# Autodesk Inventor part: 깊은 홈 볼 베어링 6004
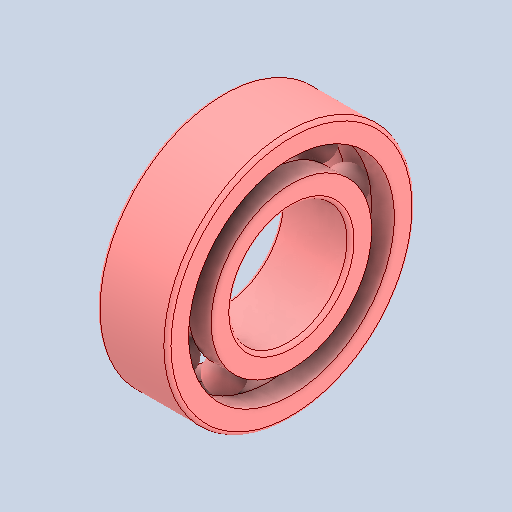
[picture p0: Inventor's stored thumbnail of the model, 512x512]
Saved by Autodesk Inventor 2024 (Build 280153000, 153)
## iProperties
Created: 2025-11
Part Number: 깊은 홈 볼 베어링 6004
Material: 강철, 연강
Description: 깊은 그루브 볼 베어링
Document SubType Name: Modeling
Designer: Edu07
Density: 7.85 g/cm^3
Appearance: 기본값
Author: jhkim
Sending System: Autodesk Inventor 2026
Preprocessor: ST-DEVELOPER v20.1
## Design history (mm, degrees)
node "깊은 홈 볼 베어링 60041"
node "솔리드1"
node "솔리드2"
node "솔리드3"
node "솔리드4"
node "솔리드5"
node "솔리드6"
node "솔리드7"
node "솔리드8"
node "솔리드9"
node "솔리드10"
node "솔리드11"
body "Solid1"
node "Solid1:1"
node "Solid1:2"
node "Solid1:3"
node "Solid1:4"
node "Solid1:5"
node "Solid1:6"
node "Solid1:7"
node "Solid1:8"
node "Solid1:9"
node "Solid1:10"
